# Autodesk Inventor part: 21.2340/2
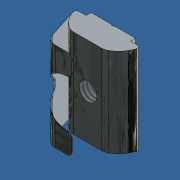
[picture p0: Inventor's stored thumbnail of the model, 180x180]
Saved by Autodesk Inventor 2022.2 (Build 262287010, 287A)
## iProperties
Created: 2012-02
Part Number: 21.2340/2
Document SubType Name: Modeling
Designer: Administrator
Density: 7.85 g/cm^3
Material: Steel
Mass: 5.23136 g
Surface Area: 8.56599 cm^2
Volume: 0.666415 cm^3
Description: M4 SQUARE NUT 30 W/ POS FXG
Appearance: Zinc
Vendor: S
Author: Administrator
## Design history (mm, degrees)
sketch "Sketch1"
  geometry: L1 (-4, 0)-(4, 0); L2 (4, 0)-(4, -0.9); L3 (-4, 0)-(-4, -0.9); L4 (-4, -0.9)-(-5.25, -0.9); L5 (4, -0.9)-(5.25, -0.9); L6 (-2.5, -4.6)-(2.5, -4.6); A1 r 5 centre (-0.966, -0.022) between (-5.726, -1.553) and (-3.522, -4.319); A2 r 5 centre (0.966, -0.022) between (3.522, -4.319) and (5.726, -1.553); A3 r 0.5 centre (5.25, -1.4) between (5.726, -1.553) and (5.25, -0.9); A4 r 0.5 centre (-5.25, -1.4) between (-5.25, -0.9) and (-5.726, -1.553); A5 r 2 centre (-2.5, -2.6) between (-3.522, -4.319) and (-2.5, -4.6); A6 r 2 centre (2.5, -2.6) between (2.5, -4.6) and (3.522, -4.319); 3 further points
  constraints: 12 end point, 12 point on circle, 8 tangent, 6 centre point, 2 equal length, 2 equal radius, 2 midpoint, 2 parallel, 2 perpendicular, 1 coincident, 1 collinear, 1 horizontal, 1 vertical alignment
  dimensions: "d0" = 0.9 distance of L1.end L2.end; "d1" = 8 distance of L1.start L1.end; "d2" = 4.6 distance between parallel lines of L6 L1; "d4" = 5 radius of A1; "d5" = 5 radius of A2 (= d4); "d6" = 0.5 radius of A3; "d7" = 2 radius of A5; "d8" = 11.5 dimension on A3 A4; "d9" = 5 distance of L6.start L6.end
extrude "Extrusion1" new body sketch "Sketch1" stored distance "d10" = 16; taper "d11" = 0 deg
sketch "Sketch2"
  geometry: L1 (-4, 0)-(4, 0) reference; L2 (-0.25, 0)-(0, -0.25); L3 (0, -0.25)-(0.25, 0); 2 further points
  constraints: 4 end point, 2 point on line, 1 midpoint, 1 vertical alignment
  dimensions: "d12" = 45 deg angle of L1 L2; "d13" = 90 deg angle of L3 L2; "d14" = 0.25 distance from line of L2.end L1
extrude "Extrusion2" cut sketch "Sketch2" extent not by distance; stored distance "d15" = 16; taper "d16" = 0 deg
fillet "Fillet1" dims "d17" = 0.2
sketch "Sketch3"
  geometry: 2 further points
  constraints: 1 coincident
hole "Hole1" sketch "Sketch3" at (4, 8) diameter "d18" = 3.242; stored, may be unused: countersink angle "d22" = 90 deg, drill point angle "d24" = 118 deg; dims "d19" = 6, "d20" = 4, "d21" = 2, "d23" = 8
sketch "Sketch4"
  geometry: L1 (-5.726, -1.553)-(-4.005, -6.901); L2 (-2.102, -8.288)-(0.898, -8.288); L3 (-4, 0)-(-0.25, 0) reference; L4 (0.898, -8.368)-(-2.102, -8.368); L5 (-4.082, -6.925)-(-5.802, -1.578); L6 (-5.802, -1.578)-(-5.726, -1.553); L7 (0.898, -8.288)-(0.898, -8.368); L8 (-4, -0.9)-(-5.25, -0.9) reference; A1 r 2 centre (-2.102, -6.288) between (-4.005, -6.901) and (-2.102, -8.288); A2 r 2.08 centre (-2.102, -6.288) between (-4.082, -6.925) and (-2.102, -8.368); A3 r 5 centre (-0.966, -0.022) between (-5.726, -1.553) and (-3.522, -4.319) reference; 1 further point
  constraints: 12 end point, 4 point on circle, 3 tangent, 2 centre point, 2 perpendicular, 1 horizontal, 2 other
  dimensions: "d26" = 2 radius of A1; "d27" = 0.08 distance between parallel lines of L5 L1; "d28" = 3 distance of L4.start L4.end; "d35" = 7.468 distance between parallel lines of L4 L8
extrude "Extrusion3" join sketch "Sketch4" stored distance "d29" = 16; taper "d30" = 0 deg
sketch "Sketch5"
  geometry: L1 (5, 0)-(5, -16) reference; L2 (2.5, -12.25)-(15.825, -12.25); L3 (15.825, -12.25)-(15.825, -3.75); L4 (15.825, -3.75)-(2.5, -3.75); C1 r 1.621 at (2.5, -8) reference; A1 r 4.25 centre (2.5, -8) between (2.5, -3.75) and (2.5, -12.25)
  constraints: 6 end point, 2 point on circle, 2 tangent, 1 centre point, 1 coincident, 1 perpendicular, 1 vertical, 1 vertical alignment
  dimensions: "d31" = 8.5 diameter of A1
extrude "Extrusion4" cut sketch "Sketch5" distance "d32" = 16; taper "d33" = 0 deg
fillet "Fillet2" dims "d34" = 1
body "Solid1"
